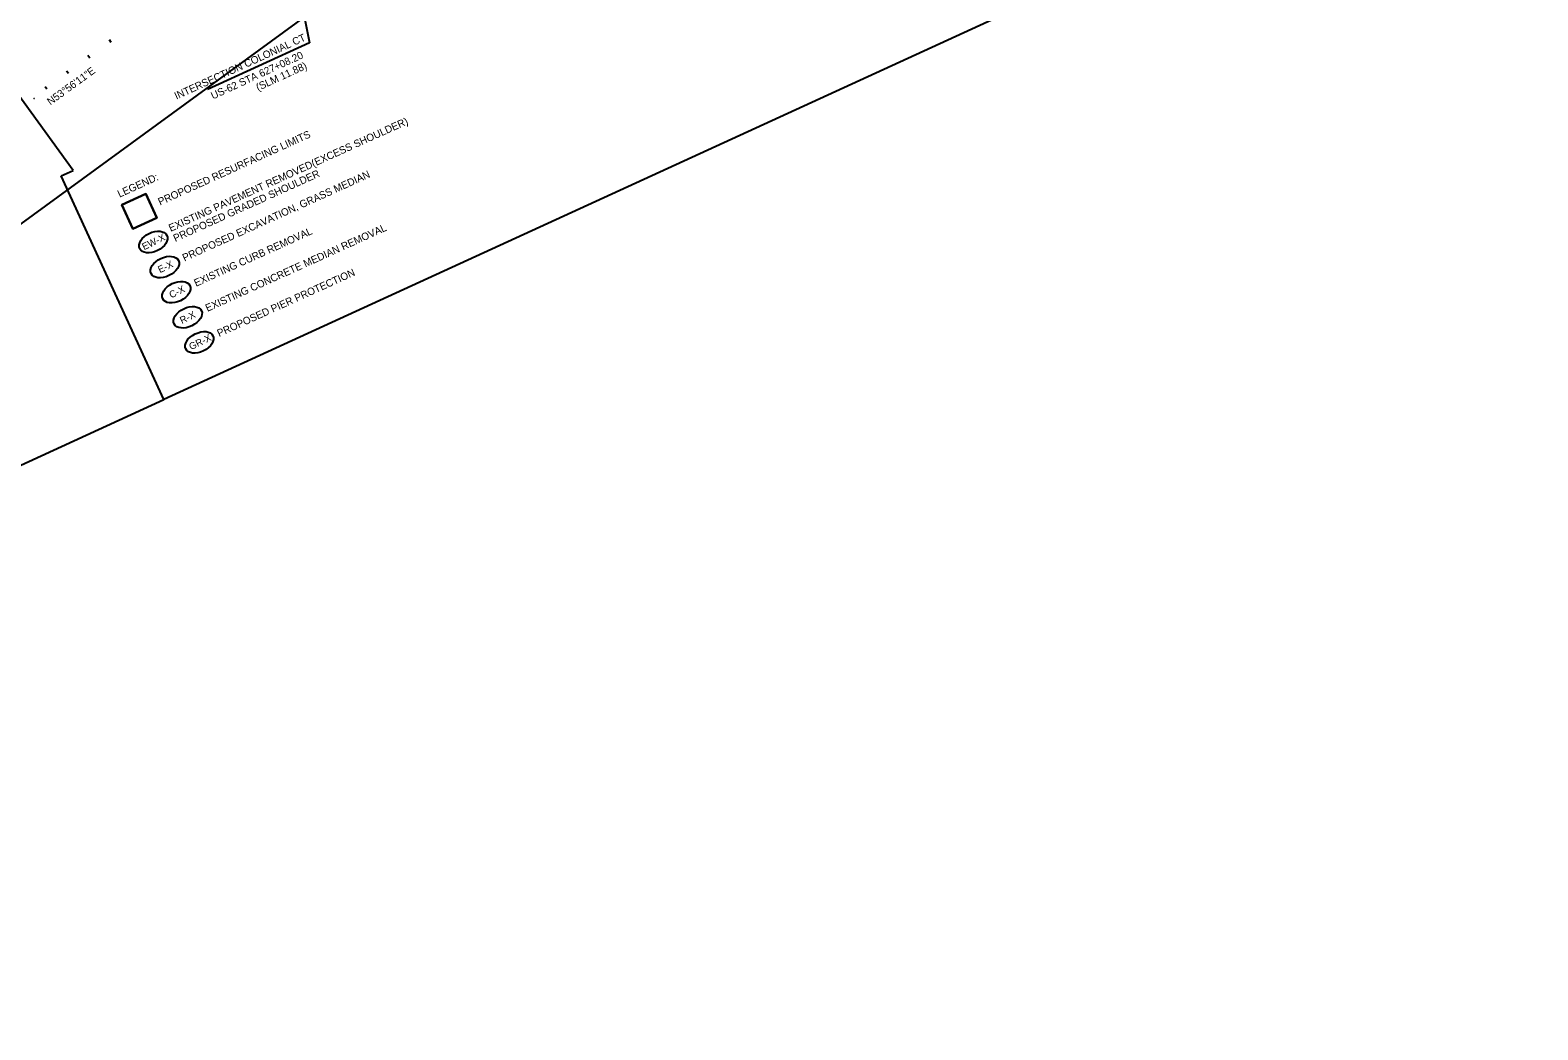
# Model space of a CAD drawing. Extents: x 127199 to 143299, y 479188 to 491521.
# Drawn here: x 133628 to 139313, y 479188 to 482957 of the extents above; entities that cross this region are included whole.
import ezdxf

# ---------------------------------------------------------------- set-up
doc = ezdxf.new("R2010")
doc.units = 0
for name, color, linetype in [('BD_X_Building', 7, 'Continuous'), ('PM_P_CL_Double_Solid', 7, 'Continuous'), ('PM_X_CL_Pass_Proh_Lt', 7, 'Continuous'), ('PM_X_Lane_Line', 7, 'Continuous'), ('PV_X_Parking_Lot', 7, 'Continuous'), ('PV_X_Walk', 7, 'Continuous'), ('RD_X_RR_2', 7, 'Continuous'), ('SH_Data', 7, 'Continuous')]:
    doc.layers.add(name, color=color, linetype=linetype)

msp = doc.modelspace()

# ---------------------------------------------------------------- linework, layer by layer
at = {"layer": 'BD_X_Building'}
msp.add_circle((133642.8, 482698.7), 0.05, dxfattribs=at)
at = {"layer": 'PM_P_CL_Double_Solid'}
msp.add_lwpolyline([(134105.5, 482248.9), (134014.6, 482207.2), (133972.9, 482298.1), (134063.8, 482339.8)], close=True, dxfattribs=at)
at = {"layer": 'PM_X_CL_Pass_Proh_Lt'}
for centre, major_axis in [((134092.1, 482158.2), (51.4, 24.9)), ((134135.5, 482063.6), (51.7, 24.5)), ((134178.9, 481968.9), (51.4, 24.9)), ((134222.3, 481874.3), (-51.4, -24.9)), ((134265.7, 481779.7), (51.4, 24.9))]:
    msp.add_ellipse(centre, major_axis=major_axis, ratio=0.62608, dxfattribs=at)
at = {"layer": 'PM_X_Lane_Line'}
for p, q in [((134587.1, 483386.3), (134681.2, 482909.1)), ((134681.2, 482909.1), (134297.1, 482732.9))]:
    msp.add_line(p, q, dxfattribs=at)
at = {"layer": 'PV_X_Walk'}
for p, q in [((133933.8, 482910.5), (133926.7, 482920.2)), ((133852.9, 482851.7), (133845.9, 482861.4)), ((133772.1, 482792.8), (133765, 482802.5)), ((133691.3, 482733.9), (133684.2, 482743.6))]:
    msp.add_line(p, q, dxfattribs=at)
at = {"layer": 'RD_X_RR_2'}
for p, q in [((137214.6, 484869.1), (131432.3, 480651.5)), ((139312.6, 483940), (134131.4, 481564)), ((133790.3, 482428.1), (133437.1, 482913.1)), ((133790.3, 482428.1), (133437.1, 482913.1)), ((133744.7, 482407.2), (133790.3, 482428.1)), ((133744.7, 482407.2), (133790.3, 482428.1)), ((134131.4, 481564), (133744.7, 482407.2)), ((134131.4, 481564), (133744.7, 482407.2)), ((128950.3, 479187.9), (134131.4, 481564))]:
    msp.add_line(p, q, dxfattribs=at)
at = {"layer": 'SH_Data'}
msp.add_lwpolyline([(134063.8, 482339.8), (133972.9, 482298.1), (134014.6, 482207.2), (134105.5, 482248.9)], close=True, dxfattribs=at)

# ---------------------------------------------------------------- texts
at = {"layer": 'PM_X_CL_Pass_Proh_Lt'}
for s, height, rotation, p in [('EXISTING PAVEMENT REMOVED(EXCESS SHOULDER)', 28, 24.3908, (134157.8, 482196.2)), ('PROPOSED RESURFACING LIMITS', 28, 24.3908, (134117.6, 482295.4)), ('LEGEND:', 28, 24.3908, (133964.7, 482325.1)), ('PROPOSED GRADED SHOULDER', 28, 24.3908, (134175.1, 482157.9)), ('PROPOSED EXCAVATION, GRASS MEDIAN', 28, 24.3908, (134209.5, 482084.4)), ('EW-X', 26.25, 25.8512, (134057.3, 482126.7)), ('EXISTING CURB REMOVAL', 28, 24.3908, (134253.2, 481989)), ('EXISTING CONCRETE MEDIAN REMOVAL', 28, 24.3908, (134296.3, 481894.5)), ('E-X', 26.25, 25.3596, (134117, 482040.3)), ('PROPOSED PIER PROTECTION', 28, 24.3908, (134340.3, 481799.7)), ('C-X', 26.25, 25.8512, (134159.8, 481945.1)), ('R-X', 26.25, 25.8512, (134199.9, 481848.9)), ('GR-X', 26.25, 25.8512, (134234.6, 481750.1))]:
    msp.add_text(s, height=height, rotation=rotation, dxfattribs=at).set_placement(p)
at = {"layer": 'PM_X_Lane_Line'}
for s, p in [('INTERSECTION COLONIAL CT', (134179.5, 482694.4)), ('US-62 STA 627+08.20', (134317.1, 482695.2)), ('(SLM 11.88)', (134487.1, 482726.9))]:
    msp.add_text(s, height=28, rotation=24.6363, dxfattribs=at).set_placement(p)
at = {"layer": 'PV_X_Parking_Lot'}
msp.add_text('N53°56\'11"E', height=28, rotation=36.0636, dxfattribs=at).set_placement((133704.1, 482672.7))

doc.saveas('drawing.dxf')
